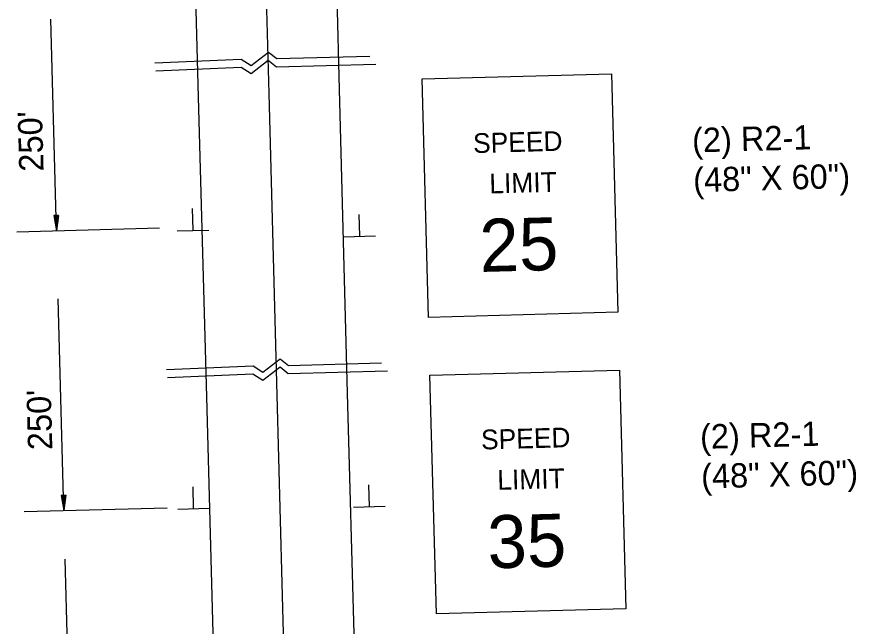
# Model space of a CAD drawing. Extents: x 1929624 to 1936506, y 596315 to 605721.
# Drawn here: x 1929786 to 1929997.7, y 598348.6 to 598502.4 of the extents above; entities that cross this region are included whole.
import ezdxf

# ---------------------------------------------------------------- set-up
doc = ezdxf.new("R2010")
doc.units = 0
doc.layers.add('Default', color=7, linetype='Continuous')

msp = doc.modelspace()

# ---------------------------------------------------------------- linework, layer by layer
at = {"layer": 'Default'}
for p, q in [((1929831.84, 598482.11), (1929830.14, 598545.5)), ((1929849.61, 598483.05), (1929847.93, 598545.63)), ((1929867.38, 598484), (1929865.73, 598545.76)), ((1929795.98, 598448.4), (1929794.55, 598501.79)), ((1929869.44, 598407.43), (1929867.38, 598484)), ((1929833.87, 598406.48), (1929831.84, 598482.11)), ((1929851.66, 598406.95), (1929849.61, 598483.05)), ((1929830.44, 598448.51), (1929830.29, 598453.98)), ((1929796.45, 598452.26), (1929795.3, 598452.22)), ((1929795.3, 598452.22), (1929795.98, 598448.4)), ((1929795.4, 598452.23), (1929795.96, 598449.05)), ((1929795.5, 598452.23), (1929795.95, 598449.7)), ((1929795.59, 598452.23), (1929795.93, 598450.34)), ((1929795.69, 598452.24), (1929795.91, 598450.99)), ((1929795.79, 598452.24), (1929795.89, 598451.63)), ((1929795.97, 598452.24), (1929795.89, 598451.63)), ((1929796.06, 598452.25), (1929795.91, 598450.99)), ((1929796.16, 598452.25), (1929795.93, 598450.34)), ((1929796.26, 598452.25), (1929795.95, 598449.7)), ((1929796.36, 598452.25), (1929795.96, 598449.05)), ((1929796.45, 598452.26), (1929795.98, 598448.4)), ((1929872.5, 598447.01), (1929872.35, 598452.47)), ((1929785.97, 598448.14), (1929821.98, 598449.1)), ((1929834.42, 598448.5), (1929826.42, 598448.29)), ((1929876.48, 598447), (1929868.48, 598446.78)), ((1929797.87, 598377.82), (1929796.44, 598431.2)), ((1929871.33, 598336.85), (1929869.44, 598407.43)), ((1929835.77, 598335.89), (1929833.87, 598406.48)), ((1929853.55, 598336.37), (1929851.66, 598406.95)), ((1929830.58, 598378.33), (1929830.43, 598383.79)), ((1929874.91, 598378.83), (1929874.76, 598384.29)), ((1929798.35, 598381.67), (1929797.2, 598381.64)), ((1929797.2, 598381.64), (1929797.87, 598377.82)), ((1929797.29, 598381.64), (1929797.86, 598378.46)), ((1929797.39, 598381.65), (1929797.84, 598379.12)), ((1929797.49, 598381.65), (1929797.82, 598379.76)), ((1929797.58, 598381.65), (1929797.81, 598380.41)), ((1929797.68, 598381.65), (1929797.79, 598381.05)), ((1929797.86, 598381.66), (1929797.79, 598381.05)), ((1929797.96, 598381.66), (1929797.81, 598380.41)), ((1929798.06, 598381.66), (1929797.82, 598379.76)), ((1929798.15, 598381.67), (1929797.84, 598379.12)), ((1929798.25, 598381.67), (1929797.86, 598378.46)), ((1929798.35, 598381.67), (1929797.87, 598377.82)), ((1929787.86, 598377.55), (1929823.88, 598378.52)), ((1929834.56, 598378.32), (1929826.56, 598378.11)), ((1929878.89, 598378.82), (1929870.89, 598378.6)), ((1929799.64, 598312.19), (1929798.2, 598365.57))]:
    msp.add_line(p, q, dxfattribs=at)
for points in [[(1929820.81, 598490.8), (1929842.59, 598491.72), (1929845.11, 598490.12), (1929849.45, 598493.48), (1929851.54, 598491.83), (1929875.03, 598492.46)], [(1929821.06, 598488.77), (1929842.56, 598489.67), (1929845.08, 598488.08), (1929849.42, 598491.43), (1929851.51, 598489.78), (1929876.53, 598490.45)], [(1929823.77, 598413.41), (1929845.56, 598414.33), (1929848.07, 598412.73), (1929852.41, 598416.09), (1929854.5, 598414.44), (1929878, 598415.07)], [(1929824.02, 598411.38), (1929845.53, 598412.28), (1929848.04, 598410.69), (1929852.38, 598414.04), (1929854.47, 598412.39), (1929879.49, 598413.06)]]:
    msp.add_lwpolyline(points, dxfattribs=at)
for points in [[(1929935.98, 598488.03), (1929937.6, 598427.82), (1929889.82, 598426.53), (1929888.2, 598486.75)], [(1929937.99, 598413.25), (1929939.6, 598353.03), (1929891.83, 598351.75), (1929890.21, 598411.96)]]:
    msp.add_lwpolyline(points, close=True, dxfattribs=at)

# ---------------------------------------------------------------- texts
for s, height, rotation, p in [("250'", 6.14, 91.5377, (1929792.73, 598463.4)), ('(2) R2-1', 6.14, 1.5377, (1929956.41, 598468.15)), ('SPEED', 4.978, 1.5377, (1929901.14, 598467.99)), ('(48" X 60")', 6.1396, 1.5377, (1929956.68, 598458.14)), ('LIMIT', 4.978, 1.5377, (1929905.24, 598457.8)), ('25', 13.342, 1.5377, (1929902.88, 598437.99)), ("250'", 6.14, 91.5377, (1929794.95, 598393.14)), ('SPEED', 4.978, 1.5377, (1929903.15, 598393.2)), ('(2) R2-1', 6.14, 1.5377, (1929958.42, 598393.36)), ('(48" X 60")', 6.1396, 1.5377, (1929958.69, 598383.36)), ('LIMIT', 4.978, 1.5377, (1929907.25, 598383.02)), ('35', 13.342, 1.5377, (1929904.88, 598363.2))]:
    msp.add_text(s, height=height, rotation=rotation, dxfattribs=at).set_placement(p)

doc.saveas('drawing.dxf')
